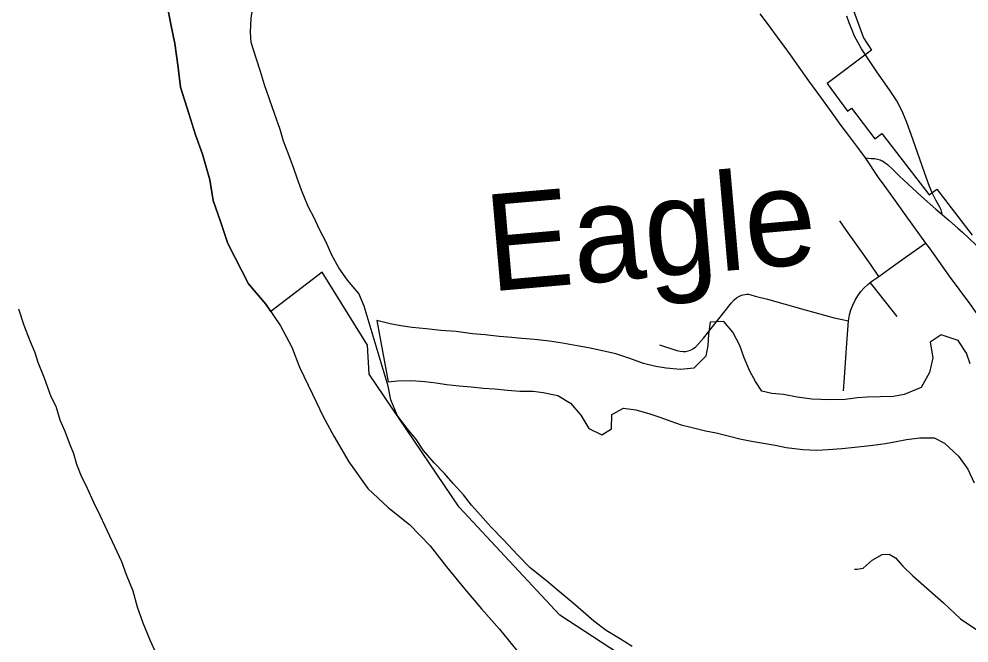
# Model space of a CAD drawing. Extents: x 0 to 34, y 0 to 22.
# Drawn here: x 5.137 to 6.068, y 15.499 to 16.11 of the extents above; entities that cross this region are included whole.
import ezdxf

# ---------------------------------------------------------------- set-up
doc = ezdxf.new("R2010")
doc.units = 0
for name, color, linetype in [('Default', 7, 'Continuous'), ('GM_X_City_Street', 7, 'Continuous'), ('GM_X_Corporation', 7, 'Continuous'), ('GM_X_County_Road', 7, 'Continuous'), ('GM_X_Major_River', 7, 'Continuous'), ('GM_X_Minor_River', 7, 'Continuous'), ('GM_X_Minor_River_Text', 7, 'Continuous'), ('GM_X_Township_Road', 7, 'Continuous'), ('GM_X_US_Route', 7, 'Continuous'), ('SH_Cut_Line', 7, 'Continuous')]:
    doc.layers.add(name, color=color, linetype=linetype)

msp = doc.modelspace()

# ---------------------------------------------------------------- linework, layer by layer
at = {"layer": 'Default'}
msp.add_lwpolyline([(5.28182, 16.12569), (5.28598, 16.10526), (5.28974, 16.08639), (5.29314, 16.06299), (5.29544, 16.04372), (5.30349, 16.01795), (5.30996, 15.997), (5.31677, 15.97804), (5.32424, 15.95296), (5.32728, 15.93275), (5.33459, 15.91194), (5.34186, 15.89044), (5.36189, 15.85107), (5.37907, 15.83116), (5.39322, 15.80988), (5.40438, 15.78899), (5.41192, 15.76933), (5.42449, 15.74299), (5.43513, 15.72128), (5.44543, 15.70178), (5.4604, 15.67679), (5.4788, 15.65065), (5.49888, 15.63207), (5.51962, 15.61544), (5.53975, 15.5945), (5.55595, 15.57374), (5.57378, 15.55205), (5.59012, 15.53263), (5.60789, 15.51291), (5.62495, 15.492)], dxfattribs=at)
at = {"layer": 'GM_X_City_Street'}
for points in [[(5.9792, 15.85838), (5.97104, 15.87026), (5.96072, 15.885), (5.94775, 15.90322), (5.94103, 15.9129)], [(5.76448, 15.79123), (5.78164, 15.78566), (5.78468, 15.78499), (5.78777, 15.78471), (5.79026, 15.78483), (5.79269, 15.78529), (5.79503, 15.78612), (5.79722, 15.78729), (5.79969, 15.78917), (5.80274, 15.79227), (5.8076, 15.79795), (5.83513, 15.83249), (5.83766, 15.83523), (5.84002, 15.83724), (5.84212, 15.83856), (5.84497, 15.83982), (5.84796, 15.84066), (5.84979, 15.84093), (5.85164, 15.84088), (5.85387, 15.84035), (5.85839, 15.83906), (5.87019, 15.83594), (5.90731, 15.82558), (5.93546, 15.81769), (5.94358, 15.81605), (5.94975, 15.81481), (5.95074, 15.82069), (5.95205, 15.82546), (5.95376, 15.83011), (5.95618, 15.83513), (5.9587, 15.83939), (5.9616, 15.8434), (5.9649, 15.8471), (5.96854, 15.85047), (5.97089, 15.8523), (5.97344, 15.85429), (5.9792, 15.85838), (5.9937, 15.86867), (6.00737, 15.87836), (6.02518, 15.89097)], [(5.9973, 15.81918), (5.9737, 15.84878), (5.97089, 15.8523)], [(5.94477, 15.74624), (5.94567, 15.75926), (5.94736, 15.7834), (5.94839, 15.79706), (5.94975, 15.81481)], [(5.95545, 15.57149), (5.95813, 15.57149), (5.96388, 15.57264), (5.9727, 15.58031), (5.98266, 15.58606), (5.98955, 15.58644), (5.99569, 15.58261), (6.00297, 15.57456), (6.01255, 15.56498), (6.04282, 15.53853), (6.0593, 15.52283), (6.07425, 15.51286), (6.08191, 15.51171), (6.09072, 15.51516), (6.10223, 15.52895), (6.11756, 15.54774), (6.12943, 15.55961), (6.14285, 15.57188), (6.15434, 15.58069), (6.185, 15.61212), (6.20685, 15.63434), (6.20913, 15.63683)]]:
    msp.add_lwpolyline(points, dxfattribs=at)
at = {"layer": 'GM_X_Corporation'}
for points in [[(5.80342, 16.93855), (5.66203, 16.85355), (5.65541, 16.84979), (5.72228, 16.7126), (5.74404, 16.65924), (5.77943, 16.67856), (6.01403, 16.25974), (5.94106, 16.22084), (5.9447, 16.20762), (5.95237, 16.1249), (5.96446, 16.0921), (5.97231, 16.07998), (5.92869, 16.04718), (5.94871, 16.02005), (5.95247, 16.02294), (5.97557, 15.99292), (5.98233, 15.99812), (6.02854, 15.93809), (6.03604, 15.94387), (6.0707, 15.89885)], [(5.78839, 15.44725), (5.66695, 15.52655), (5.56827, 15.63228), (5.48017, 15.76268), (5.47866, 15.79106), (5.43414, 15.86233), (5.38378, 15.82409), (5.37907, 15.83116), (5.36189, 15.85107), (5.34186, 15.89044), (5.33459, 15.91194), (5.32728, 15.93275), (5.32424, 15.95296), (5.31677, 15.97804), (5.30996, 15.997), (5.30349, 16.01795), (5.29544, 16.04372), (5.29314, 16.06299), (5.28974, 16.08639), (5.28598, 16.10526), (5.28182, 16.12569)]]:
    msp.add_lwpolyline(points, dxfattribs=at)
at = {"layer": 'GM_X_County_Road'}
for points in [[(5.9659, 15.97435), (5.97199, 15.97394), (5.97542, 15.97364), (5.97687, 15.97342), (5.97801, 15.97323), (5.97934, 15.97292), (5.98053, 15.9725), (5.9818, 15.97199), (5.98307, 15.97135), (5.9843, 15.97059), (5.98778, 15.96783), (5.99283, 15.96322), (5.99993, 15.95623), (6.00351, 15.9528), (6.00803, 15.94859), (6.02116, 15.93644), (6.03508, 15.92418), (6.04131, 15.91896)], [(6.04131, 15.91896), (6.04837, 15.91305), (6.05676, 15.90568), (6.06137, 15.90151), (6.0677, 15.89556), (6.07402, 15.88961), (6.08483, 15.87944), (6.08859, 15.87627), (6.09304, 15.87304), (6.09775, 15.8702), (6.10157, 15.86831), (6.10613, 15.86657)]]:
    msp.add_lwpolyline(points, dxfattribs=at)
at = {"layer": 'GM_X_Major_River'}
msp.add_line((5.49889, 15.75078), (5.47511, 15.82928), dxfattribs=at)
for points in [[(5.47511, 15.82928), (5.46994, 15.84149), (5.45909, 15.85452), (5.4505, 15.86677), (5.44344, 15.879), (5.43789, 15.89198), (5.43158, 15.9042), (5.42677, 15.91489), (5.42046, 15.92673), (5.41381, 15.94276), (5.40977, 15.95458), (5.40646, 15.96411), (5.40094, 15.97898), (5.39614, 15.99081), (5.39285, 16.00224), (5.38734, 16.01787), (5.37779, 16.04608), (5.37376, 16.05904), (5.36972, 16.07124), (5.36459, 16.08725), (5.36394, 16.09751), (5.36447, 16.11117), (5.3665, 16.12406), (5.36779, 16.1381)], [(5.13671, 15.82664), (5.14184, 15.81063), (5.14737, 15.79613), (5.15254, 15.78392), (5.15547, 15.7744), (5.16175, 15.75914), (5.16837, 15.74083), (5.1732, 15.73128), (5.17722, 15.71795), (5.18202, 15.70688), (5.18645, 15.69544), (5.1905, 15.68476), (5.19342, 15.67447), (5.19785, 15.66379), (5.20378, 15.65081), (5.21007, 15.63707), (5.21637, 15.62446), (5.22119, 15.61416), (5.23304, 15.58896), (5.23748, 15.57903), (5.24227, 15.56645), (5.24854, 15.55043), (5.25292, 15.53481), (5.25844, 15.51918), (5.26546, 15.50239), (5.27137, 15.48865)], [(5.73789, 15.49591), (5.72547, 15.50365), (5.71229, 15.51139), (5.70027, 15.52064), (5.68976, 15.52987), (5.68, 15.53834), (5.6661, 15.54989), (5.65371, 15.56029), (5.63793, 15.573), (5.62556, 15.58567), (5.6117, 15.60026), (5.59934, 15.61293), (5.58923, 15.62443), (5.58024, 15.63441), (5.57239, 15.64437), (5.56228, 15.6555), (5.55367, 15.66547), (5.54393, 15.67584), (5.53345, 15.68773), (5.526, 15.6992), (5.51702, 15.70956), (5.50768, 15.72258), (5.5014, 15.73746), (5.49889, 15.75078)]]:
    msp.add_lwpolyline(points, dxfattribs=at)
at = {"layer": 'GM_X_Minor_River'}
msp.add_line((5.48782, 15.81523), (5.49874, 15.75509), dxfattribs=at)
for points in [[(6.06884, 15.77262), (6.0652, 15.78331), (6.05704, 15.79558), (6.04044, 15.80114), (6.02972, 15.79408), (6.03215, 15.77847), (6.0289, 15.76408), (6.02073, 15.74939), (6.00433, 15.74278), (5.99368, 15.74066), (5.98078, 15.74047), (5.96788, 15.7399), (5.9584, 15.73927), (5.94624, 15.73793), (5.93145, 15.73739), (5.91364, 15.73802), (5.89926, 15.74013), (5.88602, 15.74261), (5.87466, 15.74353), (5.86484, 15.74595), (5.85853, 15.75554), (5.85299, 15.7655), (5.84749, 15.77849), (5.84312, 15.79071), (5.83648, 15.80373), (5.82754, 15.81412), (5.81426, 15.81355), (5.81257, 15.80179), (5.81203, 15.79079), (5.80998, 15.78018), (5.79806, 15.76857), (5.78515, 15.76724), (5.77114, 15.76858), (5.76092, 15.77025), (5.74883, 15.77309), (5.73563, 15.77784), (5.72167, 15.7826), (5.70882, 15.78544), (5.69483, 15.7883), (5.68387, 15.79036), (5.66949, 15.79285), (5.65663, 15.79494), (5.64225, 15.79666), (5.62975, 15.7976), (5.6199, 15.79851), (5.60741, 15.79945), (5.59378, 15.80116), (5.58128, 15.8021), (5.56539, 15.80423), (5.55023, 15.80521), (5.53585, 15.80694), (5.52222, 15.80827), (5.51125, 15.80995), (5.50066, 15.81201), (5.48782, 15.81523)], [(5.49874, 15.75509), (5.50781, 15.75606), (5.52146, 15.75624), (5.53472, 15.75529), (5.5457, 15.75399), (5.55591, 15.75232), (5.5684, 15.751), (5.58015, 15.75007), (5.59226, 15.74876), (5.60287, 15.74823), (5.61574, 15.7469), (5.62786, 15.74597), (5.64075, 15.74578), (5.65059, 15.7445), (5.66495, 15.74163), (5.67736, 15.73423), (5.68742, 15.72231), (5.6952, 15.70928), (5.708, 15.70302), (5.71756, 15.70896), (5.71777, 15.72301), (5.72923, 15.7293), (5.74134, 15.72761), (5.75418, 15.724), (5.76475, 15.72043), (5.77455, 15.71687), (5.78587, 15.71291), (5.79645, 15.71047), (5.80968, 15.70724), (5.81988, 15.70519), (5.83311, 15.70196), (5.8433, 15.69916), (5.85465, 15.69709), (5.86448, 15.69543), (5.87772, 15.69296), (5.88868, 15.6909), (5.90496, 15.68876), (5.9186, 15.68819), (5.9296, 15.68879), (5.94327, 15.68973), (5.9558, 15.69106), (5.97099, 15.69274), (5.98581, 15.69481), (5.99645, 15.69655), (6.00634, 15.69869), (6.01963, 15.70039), (6.03366, 15.70019), (6.04382, 15.6951), (6.05729, 15.68237), (6.06658, 15.6697), (6.07283, 15.65631)]]:
    msp.add_lwpolyline(points, dxfattribs=at)
at = {"layer": 'GM_X_Township_Road'}
for points in [[(5.96636, 16.07541), (5.96249, 16.08125), (5.95873, 16.08763), (5.95565, 16.09375), (5.95326, 16.09948), (5.95018, 16.10672), (5.94787, 16.11324)], [(6.0317, 15.94032), (6.02897, 15.94653), (6.02589, 15.95462), (6.01976, 15.97221), (6.01266, 15.99267), (6.00667, 16.00921), (6.00273, 16.01868), (5.99987, 16.0248), (5.99685, 16.03025), (5.99323, 16.0361), (5.98985, 16.04103), (5.97742, 16.05871), (5.96636, 16.07541)], [(6.04131, 15.91896), (6.04092, 15.92092), (6.04029, 15.92349), (6.03916, 15.92609), (6.03522, 15.93309), (6.0317, 15.94032)]]:
    msp.add_lwpolyline(points, dxfattribs=at)
at = {"layer": 'GM_X_US_Route'}
for points in [[(5.86269, 16.11548), (5.86793, 16.10858), (5.87349, 16.10113), (5.87977, 16.09268), (5.88639, 16.08371), (5.89255, 16.07516), (5.89869, 16.0666), (5.91035, 16.04978), (5.92216, 16.0338), (5.93155, 16.02087), (5.94215, 16.00624), (5.95062, 15.99499), (5.95835, 15.98448), (5.9659, 15.97435)], [(5.9659, 15.97435), (5.97881, 15.95511), (5.9842, 15.94774)], [(5.9842, 15.94774), (5.99379, 15.93463), (6.00594, 15.91771), (6.02518, 15.89097)], [(6.02518, 15.89097), (6.02771, 15.88746), (6.03432, 15.87845), (6.04837, 15.85872), (6.06821, 15.83166), (6.07364, 15.82408), (6.08561, 15.80746), (6.09111, 15.80007), (6.1075, 15.77804), (6.12734, 15.75021), (6.14487, 15.72609), (6.17654, 15.68227), (6.19764, 15.65306), (6.20913, 15.63683)]]:
    msp.add_lwpolyline(points, dxfattribs=at)
at = {"layer": 'SH_Cut_Line'}
msp.add_lwpolyline([(5.28182, 16.12569), (5.28598, 16.10526), (5.28974, 16.08639), (5.29314, 16.06299), (5.29544, 16.04372), (5.30349, 16.01795), (5.30996, 15.997), (5.31677, 15.97804), (5.32424, 15.95296), (5.32728, 15.93275), (5.33459, 15.91194), (5.34186, 15.89044), (5.36189, 15.85107), (5.37907, 15.83116), (5.39322, 15.80988), (5.40438, 15.78899), (5.41192, 15.76933), (5.42449, 15.74299), (5.43513, 15.72128), (5.44543, 15.70178), (5.4604, 15.67679), (5.4788, 15.65065), (5.49888, 15.63207), (5.51962, 15.61544), (5.53975, 15.5945), (5.55595, 15.57374), (5.57378, 15.55205), (5.59012, 15.53263), (5.60789, 15.51291), (5.62495, 15.492)], dxfattribs=at)

# ---------------------------------------------------------------- texts
at = {"layer": 'GM_X_Minor_River_Text'}
msp.add_text('Eagle', height=0.094691, rotation=5.0025, dxfattribs=at).set_placement((5.59853, 15.84345))

doc.saveas('drawing.dxf')
